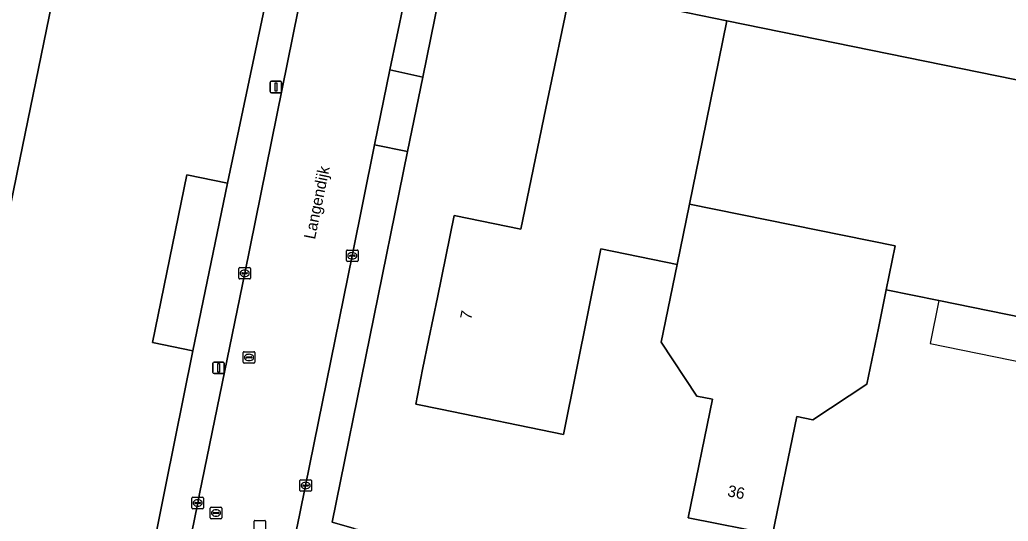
# Model space of a CAD drawing. Extents: x 157692 to 159674, y 381452 to 383291.
# Drawn here: x 158074.3 to 158160.8, y 381881.5 to 381925.4 of the extents above; entities that cross this region are included whole.
import ezdxf

# ---------------------------------------------------------------- set-up
doc = ezdxf.new("R2010")
doc.units = 0
for name, color, linetype in [('IMGEO_Erf', 7, 'Continuous'), ('IMGEO_Kolk', 7, 'Continuous'), ('IMGEO_Lichtmast', 7, 'Continuous'), ('IMGEO_Openbare_ruimte_label', 7, 'Continuous'), ('IMGEO_Pand', 7, 'Continuous'), ('IMGEO_Pand_nummerreeks', 7, 'Continuous'), ('IMGEO_Pand_overbouw', 7, 'Continuous'), ('IMGEO_Rijbaan_lokaal_gesloten', 7, 'Continuous'), ('IMGEO_Rioolput', 7, 'Continuous'), ('IMGEO_Voetpad_open', 7, 'Continuous')]:
    doc.layers.add(name, color=color, linetype=linetype)

msp = doc.modelspace()

# ---------------------------------------------------------------- linework, layer by layer
at = {"layer": 'IMGEO_Erf'}
for points in [[(158094.319, 382010.896), (158079.649, 381939.178), (158074.09, 381912.003), (158070.771, 381895.776), (157940.465, 381922.271), (157964.027, 382037.391)], [(158088.925, 381911.805), (158092.48, 381911.08), (158096.169, 381928.502), (158099.982, 381947.1), (158103.754, 381965.437), (158107.527, 381984.069)], [(158120.644, 381974.489), (158119.054, 381966.712), (158111.645, 381930.552), (158109.555, 381920.351), (158108.214, 381913.847), (158101.637, 381881.433), (158103.57, 381880.897), (158105.432, 381880.499), (158105.527, 381880.719), (158125.96, 381875.333), (158144.779, 381868.849), (158152.635, 381866.121), (158152.79, 381866.076), (158175.894, 381855.545), (158181.715, 381852.892), (158181.907, 381852.815), (158201.637, 381844.863), (158208.362, 381842.809), (158208.31, 381842.627), (158217.316, 381839.906), (158270.263, 381825.792)], [(158184.121, 381894.823), (158154.699, 381900.804), (158150.089, 381901.741), (158149.404, 381898.409), (158148.396, 381893.511), (158143.672, 381890.398), (158142.279, 381890.684), (158140.153, 381880.347), (158132.778, 381881.818), (158134.901, 381892.186), (158133.538, 381892.467), (158130.421, 381897.187), (158131.806, 381903.957), (158125.129, 381905.329), (158121.859, 381889.092), (158111.126, 381891.312), (158108.952, 381891.762), (158109.544, 381894.79), (158110.094, 381897.451), (158110.842, 381901.073), (158112.312, 381908.256), (158118.152, 381907.045), (158120.337, 381917.624), (158122.497, 381928.081), (158136.166, 381925.258), (158192.825, 381913.715)], [(158075.628, 381827.934), (158077.048, 381834.888), (158079.616, 381847.467), (158081.414, 381856.37), (158087.078, 381884.542), (158089.467, 381896.422), (158085.937, 381897.157), (158088.925, 381911.805)]]:
    msp.add_lwpolyline(points, dxfattribs=at)
at = {"layer": 'IMGEO_Kolk'}
for p, q in [((158102.9, 381904.302), (158102.9, 381905.154)), ((158102.975, 381905.228), (158103.827, 381905.228)), ((158103.388, 381905.008), (158103.413, 381905.008)), ((158103.901, 381905.154), (158103.901, 381904.302)), ((158103.827, 381904.228), (158102.975, 381904.228)), ((158103.159, 381904.722), (158103.159, 381904.734)), ((158103.597, 381904.685), (158103.199, 381904.685)), ((158103.202, 381904.771), (158103.6, 381904.771)), ((158103.411, 381904.448), (158103.386, 381904.448)), ((158103.643, 381904.734), (158103.643, 381904.722)), ((158093.492, 381902.773), (158093.492, 381903.625)), ((158093.567, 381903.699), (158094.419, 381903.699)), ((158093.751, 381903.193), (158093.751, 381903.205)), ((158093.794, 381903.242), (158094.192, 381903.242)), ((158093.98, 381903.479), (158094.005, 381903.479)), ((158094.235, 381903.205), (158094.235, 381903.193)), ((158094.493, 381903.625), (158094.493, 381902.773)), ((158094.419, 381902.699), (158093.567, 381902.699)), ((158094.189, 381903.156), (158093.791, 381903.156)), ((158094.003, 381902.919), (158093.978, 381902.919)), ((158098.823, 381884.215), (158098.823, 381885.067)), ((158098.898, 381885.141), (158099.75, 381885.141)), ((158099.824, 381885.067), (158099.824, 381884.215)), ((158099.082, 381884.635), (158099.082, 381884.647)), ((158099.52, 381884.598), (158099.122, 381884.598)), ((158099.125, 381884.684), (158099.523, 381884.684)), ((158099.334, 381884.361), (158099.309, 381884.361)), ((158099.311, 381884.921), (158099.336, 381884.921)), ((158099.566, 381884.647), (158099.566, 381884.635)), ((158089.38, 381882.69), (158089.38, 381883.542)), ((158089.455, 381883.616), (158090.307, 381883.616)), ((158089.868, 381883.396), (158089.893, 381883.396)), ((158090.381, 381883.542), (158090.381, 381882.69)), ((158099.75, 381884.141), (158098.898, 381884.141)), ((158090.307, 381882.616), (158089.455, 381882.616)), ((158089.639, 381883.11), (158089.639, 381883.122)), ((158090.077, 381883.073), (158089.679, 381883.073)), ((158089.682, 381883.159), (158090.08, 381883.159)), ((158089.891, 381882.836), (158089.866, 381882.836)), ((158090.123, 381883.122), (158090.123, 381883.11))]:
    msp.add_line(p, q, dxfattribs=at)
for points in [[(158102.9, 381904.302), (158102.9, 381905.154)], [(158102.975, 381905.228), (158103.827, 381905.228)], [(158103.901, 381905.154), (158103.901, 381904.302)], [(158103.827, 381904.228), (158102.975, 381904.228)], [(158093.492, 381902.773), (158093.492, 381903.625)], [(158093.567, 381903.699), (158094.419, 381903.699)], [(158094.493, 381903.625), (158094.493, 381902.773)], [(158094.419, 381902.699), (158093.567, 381902.699)], [(158098.823, 381884.215), (158098.823, 381885.067)], [(158098.898, 381885.141), (158099.75, 381885.141)], [(158099.824, 381885.067), (158099.824, 381884.215)], [(158089.38, 381882.69), (158089.38, 381883.542)], [(158089.455, 381883.616), (158090.307, 381883.616)], [(158090.381, 381883.542), (158090.381, 381882.69)], [(158099.75, 381884.141), (158098.898, 381884.141)], [(158090.307, 381882.616), (158089.455, 381882.616)]]:
    msp.add_lwpolyline(points, dxfattribs=at)
for centre, radius, start, end in [((158102.977, 381905.152), 0.0765, 91.55205, 178.44795), ((158102.977, 381905.152), 0.0765, 91.55205, 178.44795), ((158103.825, 381905.152), 0.0765, 1.55205, 88.44795), ((158103.825, 381905.152), 0.0765, 1.55205, 88.44795), ((158102.977, 381904.304), 0.0765, 181.55205, 268.44795), ((158102.977, 381904.304), 0.0765, 181.55205, 268.44795), ((158103.199, 381904.731), 0.0403, 85.87752, 175.75265), ((158103.196, 381904.721), 0.0366, 178.93798, 274.71019), ((158103.6, 381904.728), 0.043, 264.86636, 352.45326), ((158103.604, 381904.733), 0.0386, 1.73085, 96.63898), ((158103.825, 381904.304), 0.0765, 271.55205, 358.44795), ((158103.825, 381904.304), 0.0765, 271.55205, 358.44795), ((158093.569, 381903.623), 0.0765, 91.55205, 178.44795), ((158093.569, 381903.623), 0.0765, 91.55205, 178.44795), ((158093.791, 381903.202), 0.0403, 85.87752, 175.75265), ((158093.788, 381903.192), 0.0366, 178.93798, 274.71019), ((158094.192, 381903.199), 0.043, 264.86636, 352.45326), ((158094.196, 381903.204), 0.0386, 1.73085, 96.63898), ((158094.417, 381903.623), 0.0765, 1.55205, 88.44795), ((158094.417, 381903.623), 0.0765, 1.55205, 88.44795), ((158093.569, 381902.775), 0.0765, 181.55205, 268.44795), ((158093.569, 381902.775), 0.0765, 181.55205, 268.44795), ((158094.417, 381902.775), 0.0765, 271.55205, 358.44795), ((158094.417, 381902.775), 0.0765, 271.55205, 358.44795), ((158098.9, 381885.065), 0.0765, 91.55205, 178.44795), ((158098.9, 381885.065), 0.0765, 91.55205, 178.44795), ((158099.748, 381885.065), 0.0765, 1.55205, 88.44795), ((158099.748, 381885.065), 0.0765, 1.55205, 88.44795), ((158098.9, 381884.217), 0.0765, 181.55205, 268.44795), ((158098.9, 381884.217), 0.0765, 181.55205, 268.44795), ((158099.122, 381884.644), 0.0403, 85.87752, 175.75265), ((158099.119, 381884.634), 0.0366, 178.93798, 274.71019), ((158099.523, 381884.641), 0.043, 264.86636, 352.45326), ((158099.527, 381884.646), 0.0386, 1.73085, 96.63898), ((158099.748, 381884.217), 0.0765, 271.55205, 358.44795), ((158099.748, 381884.217), 0.0765, 271.55205, 358.44795), ((158089.457, 381883.54), 0.0765, 91.55205, 178.44795), ((158089.457, 381883.54), 0.0765, 91.55205, 178.44795), ((158090.305, 381883.54), 0.0765, 1.55205, 88.44795), ((158090.305, 381883.54), 0.0765, 1.55205, 88.44795), ((158089.457, 381882.692), 0.0765, 181.55205, 268.44795), ((158089.457, 381882.692), 0.0765, 181.55205, 268.44795), ((158089.679, 381883.119), 0.0403, 85.87752, 175.75265), ((158089.676, 381883.109), 0.0366, 178.93798, 274.71019), ((158090.08, 381883.116), 0.043, 264.86636, 352.45326), ((158090.084, 381883.121), 0.0386, 1.73085, 96.63898), ((158090.305, 381882.692), 0.0765, 271.55205, 358.44795), ((158090.305, 381882.692), 0.0765, 271.55205, 358.44795)]:
    msp.add_arc(centre, radius, start, end, dxfattribs=at)
for centre, major_axis, ratio, start_param, end_param in [((158103.387, 381904.728), (-0.387, 0.002), 0.722429, 4.712389, 7.853982), ((158103.412, 381904.728), (-0.39, 0.002), 0.717154, 1.570796, 4.712389), ((158093.979, 381903.199), (-0.387, 0.002), 0.722429, 4.712389, 7.853982), ((158094.004, 381903.199), (-0.39, 0.002), 0.717154, 1.570796, 4.712389), ((158099.31, 381884.641), (-0.387, 0.002), 0.722429, 4.712389, 7.853982), ((158099.335, 381884.641), (-0.39, 0.002), 0.717154, 1.570796, 4.712389), ((158089.867, 381883.116), (-0.387, 0.002), 0.722429, 4.712389, 7.853982), ((158089.892, 381883.116), (-0.39, 0.002), 0.717154, 1.570796, 4.712389)]:
    msp.add_ellipse(centre, major_axis=major_axis, ratio=ratio, start_param=start_param, end_param=end_param, dxfattribs=at)
at = {"layer": 'IMGEO_Lichtmast'}
for p, q in [((158096.233, 381919.082), (158096.233, 381919.882)), ((158096.233, 381919.882), (158096.233, 381919.082)), ((158096.333, 381919.982), (158097.123, 381919.982)), ((158097.123, 381919.982), (158096.333, 381919.982)), ((158097.223, 381919.882), (158097.223, 381919.082)), ((158097.223, 381919.082), (158097.223, 381919.882)), ((158097.123, 381918.982), (158096.333, 381918.982)), ((158096.333, 381918.982), (158097.123, 381918.982)), ((158091.31, 381895.435), (158092.1, 381895.435)), ((158092.1, 381895.435), (158091.31, 381895.435)), ((158091.21, 381894.535), (158091.21, 381895.335)), ((158091.21, 381895.335), (158091.21, 381894.535)), ((158092.2, 381895.335), (158092.2, 381894.535)), ((158092.2, 381894.535), (158092.2, 381895.335)), ((158092.1, 381894.435), (158091.31, 381894.435)), ((158091.31, 381894.435), (158092.1, 381894.435))]:
    msp.add_line(p, q, dxfattribs=at)
for points in [[(158096.653, 381919.857), (158096.803, 381919.857), (158096.803, 381919.107), (158096.653, 381919.107), (158096.653, 381919.857)], [(158091.63, 381895.31), (158091.78, 381895.31), (158091.78, 381894.56), (158091.63, 381894.56), (158091.63, 381895.31)]]:
    msp.add_lwpolyline(points, dxfattribs=at)
for centre, start, end in [((158096.333, 381919.882), 90, 180), ((158096.333, 381919.882), 90, 180), ((158097.123, 381919.882), 0, 90), ((158097.123, 381919.882), 360, 90), ((158096.333, 381919.082), 180, 270), ((158096.333, 381919.082), 180, 270), ((158097.123, 381919.082), 270, 0), ((158097.123, 381919.082), 270, 0), ((158091.31, 381895.335), 90, 180), ((158091.31, 381895.335), 90, 180), ((158092.1, 381895.335), 0, 90), ((158092.1, 381895.335), 360, 90), ((158091.31, 381894.535), 180, 270), ((158091.31, 381894.535), 180, 270), ((158092.1, 381894.535), 270, 0), ((158092.1, 381894.535), 270, 0)]:
    msp.add_arc(centre, 0.1, start, end, dxfattribs=at)
at = {"layer": 'IMGEO_Pand'}
msp.add_lwpolyline([(157964.027, 382037.391), (157940.465, 381922.271), (158070.771, 381895.776), (158074.09, 381912.003), (158079.649, 381939.178), (158094.319, 382010.896)], dxfattribs=at)
for points in [[(158131.806, 381903.957), (158132.884, 381909.227), (158134.023, 381914.791), (158136.166, 381925.258), (158122.497, 381928.081), (158120.337, 381917.624), (158118.152, 381907.045), (158112.312, 381908.256), (158110.842, 381901.073), (158110.094, 381897.451), (158109.544, 381894.79), (158108.952, 381891.762), (158111.126, 381891.312), (158121.859, 381889.092), (158125.129, 381905.329)], [(158212.684, 381909.652), (158192.825, 381913.715), (158136.166, 381925.258), (158134.023, 381914.791), (158132.884, 381909.227), (158150.883, 381905.602), (158150.089, 381901.741), (158154.699, 381900.804), (158184.121, 381894.823), (158191.444, 381893.334), (158187.182, 381862.848), (158186.49, 381857.896), (158200.81, 381854.948), (158200.049, 381851.25), (158200.693, 381851.154), (158201.697, 381856.053)], [(158092.48, 381911.08), (158088.925, 381911.805), (158085.937, 381897.157), (158089.467, 381896.422)], [(158149.404, 381898.409), (158150.089, 381901.741), (158150.883, 381905.602), (158132.884, 381909.227), (158131.806, 381903.957), (158130.421, 381897.187), (158133.538, 381892.467), (158134.901, 381892.186), (158132.778, 381881.818), (158140.153, 381880.347), (158142.279, 381890.684), (158143.672, 381890.398), (158148.396, 381893.511)]]:
    msp.add_lwpolyline(points, close=True, dxfattribs=at)
at = {"layer": 'IMGEO_Pand_overbouw'}
msp.add_lwpolyline([(158154.699, 381900.804), (158153.935, 381897.071), (158183.347, 381891.046), (158184.121, 381894.823)], close=True, dxfattribs=at)
at = {"layer": 'IMGEO_Rijbaan_lokaal_gesloten'}
for points in [[(158110.401, 381983.44), (158107.08, 381967.14), (158106.63, 381964.853), (158103.023, 381947.364), (158102.858, 381946.545), (158099.043, 381927.911), (158098.681, 381926.231), (158093.994, 381903.198), (158090.046, 381883.911), (158089.883, 381883.116), (158084.29, 381855.738), (158083.809, 381853.599), (158082.429, 381846.881), (158079.85, 381834.323), (158078.425, 381827.386)], [(158087.271, 381826.269), (158093.435, 381856.17), (158098.112, 381879.211), (158098.248, 381879.541), (158098.778, 381882.055), (158099.323, 381884.642), (158103.401, 381904.728), (158105.353, 381914.424), (158106.687, 381920.975), (158107.903, 381926.804), (158112.225, 381947.864), (158116.023, 381966.537)]]:
    msp.add_lwpolyline(points, dxfattribs=at)
at = {"layer": 'IMGEO_Rioolput'}
for p, q in [((158093.871, 381895.413), (158093.871, 381896.265)), ((158093.946, 381896.339), (158094.798, 381896.339)), ((158094.872, 381896.265), (158094.872, 381895.413)), ((158094.13, 381895.833), (158094.13, 381895.845)), ((158094.568, 381895.796), (158094.17, 381895.796)), ((158094.173, 381895.882), (158094.571, 381895.882)), ((158094.382, 381895.559), (158094.357, 381895.559)), ((158094.359, 381896.119), (158094.384, 381896.119)), ((158094.614, 381895.845), (158094.614, 381895.833)), ((158094.798, 381895.339), (158093.946, 381895.339)), ((158090.983, 381881.809), (158090.983, 381882.661)), ((158091.058, 381882.735), (158091.91, 381882.735)), ((158091.471, 381882.515), (158091.496, 381882.515)), ((158091.984, 381882.661), (158091.984, 381881.809)), ((158091.91, 381881.735), (158091.058, 381881.735)), ((158091.242, 381882.229), (158091.242, 381882.241)), ((158091.68, 381882.192), (158091.282, 381882.192)), ((158091.285, 381882.278), (158091.683, 381882.278)), ((158091.494, 381881.955), (158091.469, 381881.955)), ((158091.726, 381882.241), (158091.726, 381882.229)), ((158094.892, 381881.593), (158095.744, 381881.593)), ((158094.817, 381880.667), (158094.817, 381881.519)), ((158095.818, 381881.519), (158095.818, 381880.667))]:
    msp.add_line(p, q, dxfattribs=at)
for points in [[(158093.871, 381895.413), (158093.871, 381896.265)], [(158093.946, 381896.339), (158094.798, 381896.339)], [(158094.872, 381896.265), (158094.872, 381895.413)], [(158094.798, 381895.339), (158093.946, 381895.339)], [(158090.983, 381881.809), (158090.983, 381882.661)], [(158091.058, 381882.735), (158091.91, 381882.735)], [(158091.984, 381882.661), (158091.984, 381881.809)], [(158091.91, 381881.735), (158091.058, 381881.735)], [(158094.892, 381881.593), (158095.744, 381881.593)], [(158094.817, 381880.667), (158094.817, 381881.519)], [(158095.818, 381881.519), (158095.818, 381880.667)]]:
    msp.add_lwpolyline(points, dxfattribs=at)
for centre, radius, start, end in [((158093.948, 381896.263), 0.0765, 91.55205, 178.44795), ((158093.948, 381896.263), 0.0765, 91.55205, 178.44795), ((158094.796, 381896.263), 0.0765, 1.55205, 88.44795), ((158094.796, 381896.263), 0.0765, 1.55205, 88.44795), ((158093.948, 381895.415), 0.0765, 181.55205, 268.44795), ((158093.948, 381895.415), 0.0765, 181.55205, 268.44795), ((158094.17, 381895.842), 0.0403, 85.87752, 175.75265), ((158094.167, 381895.832), 0.0366, 178.93798, 274.71019), ((158094.571, 381895.839), 0.043, 264.86636, 352.45326), ((158094.575, 381895.844), 0.0386, 1.73085, 96.63898), ((158094.796, 381895.415), 0.0765, 271.55205, 358.44795), ((158094.796, 381895.415), 0.0765, 271.55205, 358.44795), ((158091.06, 381882.659), 0.0765, 91.55205, 178.44795), ((158091.06, 381882.659), 0.0765, 91.55205, 178.44795), ((158091.908, 381882.659), 0.0765, 1.55205, 88.44795), ((158091.908, 381882.659), 0.0765, 1.55205, 88.44795), ((158091.06, 381881.811), 0.0765, 181.55205, 268.44795), ((158091.06, 381881.811), 0.0765, 181.55205, 268.44795), ((158091.282, 381882.238), 0.0403, 85.87752, 175.75265), ((158091.279, 381882.228), 0.0366, 178.93798, 274.71019), ((158091.683, 381882.235), 0.043, 264.86636, 352.45326), ((158091.687, 381882.24), 0.0386, 1.73085, 96.63898), ((158091.908, 381881.811), 0.0765, 271.55205, 358.44795), ((158091.908, 381881.811), 0.0765, 271.55205, 358.44795), ((158094.894, 381881.517), 0.0765, 91.55205, 178.44795), ((158094.894, 381881.517), 0.0765, 91.55205, 178.44795), ((158095.742, 381881.517), 0.0765, 1.55205, 88.44795), ((158095.742, 381881.517), 0.0765, 1.55205, 88.44795)]:
    msp.add_arc(centre, radius, start, end, dxfattribs=at)
for centre, major_axis, ratio, start_param, end_param in [((158094.358, 381895.839), (-0.387, 0.002), 0.722429, 4.712389, 7.853982), ((158094.383, 381895.839), (-0.39, 0.002), 0.717154, 1.570796, 4.712389), ((158091.47, 381882.235), (-0.387, 0.002), 0.722429, 4.712389, 7.853982), ((158091.495, 381882.235), (-0.39, 0.002), 0.717154, 1.570796, 4.712389)]:
    msp.add_ellipse(centre, major_axis=major_axis, ratio=ratio, start_param=start_param, end_param=end_param, dxfattribs=at)
at = {"layer": 'IMGEO_Voetpad_open'}
for points in [[(158109.555, 381920.351), (158111.645, 381930.552), (158119.054, 381966.712), (158116.186, 381967.321), (158116.023, 381966.537), (158112.225, 381947.864), (158107.903, 381926.804), (158106.687, 381920.975)], [(158087.078, 381884.542), (158081.414, 381856.37), (158079.616, 381847.467), (158082.429, 381846.881), (158083.809, 381853.599), (158084.29, 381855.738), (158089.883, 381883.116), (158090.046, 381883.911), (158093.994, 381903.198), (158098.681, 381926.231), (158099.043, 381927.911), (158096.169, 381928.502), (158092.48, 381911.08), (158089.467, 381896.422)], [(158109.555, 381920.351), (158106.687, 381920.975), (158105.353, 381914.424), (158108.214, 381913.847)]]:
    msp.add_lwpolyline(points, close=True, dxfattribs=at)
msp.add_lwpolyline([(158101.462, 381871.09), (158103.115, 381878.764), (158103.57, 381880.897), (158101.637, 381881.433), (158108.214, 381913.847), (158105.353, 381914.424), (158103.401, 381904.728), (158099.323, 381884.642), (158098.778, 381882.055), (158098.248, 381879.541)], dxfattribs=at)

# ---------------------------------------------------------------- texts
at = {"layer": 'IMGEO_Openbare_ruimte_label'}
msp.add_text('Langendijk', height=1, rotation=78.40926, dxfattribs=at).set_placement((158100.135, 381906.112))
at = {"layer": 'IMGEO_Pand_nummerreeks'}
for s, rotation, p in [('7', 78.4858, (158113.792, 381899.084)), ('36', 348.71846, (158136.149, 381883.715))]:
    msp.add_text(s, height=1, rotation=rotation, dxfattribs=at).set_placement(p)

doc.saveas('drawing.dxf')
